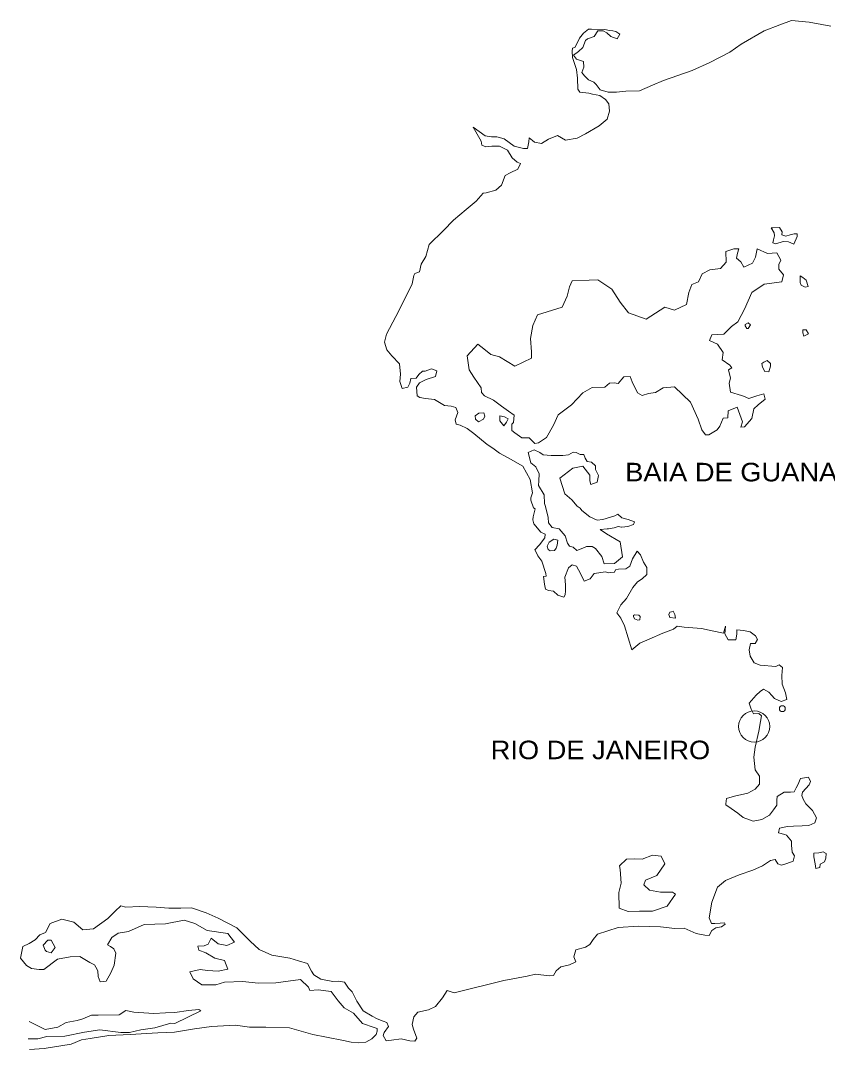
# Model space of a CAD drawing. Extents: x 47169 to 972804, y 7447977 to 9608469.
# Drawn here: x 47169 to 74653, y 7447977 to 7483012 of the extents above; entities that cross this region are included whole.
import ezdxf

# ---------------------------------------------------------------- set-up
doc = ezdxf.new("R2010")
doc.units = 0
doc.header["$LTSCALE"] = 270
doc.layers.add('1', color=7, linetype='Continuous', lineweight=13)
doc.layers.add('4', color=7, linetype='Continuous', lineweight=13)
doc.layers.add('3', color=7, linetype='Continuous')

msp = doc.modelspace()

# ---------------------------------------------------------------- linework, layer by layer
at = {"layer": '1'}
for points in [[(66771.4, 7480837.5), (66910.5, 7480652.7), (67180.5, 7480571.6), (67468.6, 7480579.8), (67786.9, 7480611), (68249.9, 7480624.2), (68697.6, 7480814.5), (69074.2, 7480969.5), (70042.9, 7481307.6), (70642.7, 7481579.9), (71333, 7481932.3), (71716.5, 7482209.5), (72496.6, 7482664.3), (73026.4, 7482867.8), (73434.2, 7483012.5), (74032.9, 7482962.6), (74467.9, 7482874.9), (74768.1, 7482816.7)], [(66647.1, 7480500.9), (66522.4, 7480541.8), (66222.7, 7480577.6), (66147.9, 7480675.4), (66137.1, 7481052.5), (66108, 7481351.4), (65972.8, 7481758.2), (65956.5, 7481968.6), (65964, 7482068.8), (66055.6, 7482104.7), (66211.7, 7482408.8), (66340.8, 7482579), (66511.9, 7482717.1), (66614.8, 7482720), (67068.2, 7482710.7), (67234.1, 7482671), (67347.6, 7482663.1), (67451.1, 7482643.9), (67577.5, 7482547.6), (67489.3, 7482389.7), (67280.9, 7482472.5), (67133.4, 7482590.4), (67018, 7482664.9), (66832.8, 7482659.6), (66704.4, 7482467.2), (66479.9, 7482394.2), (66409.4, 7482336.7), (66323.5, 7482101.2), (66172.9, 7481963.7), (66001.5, 7481836.7), (66108.5, 7481695.5), (66347.3, 7481624.6), (66353, 7481424.9), (66286.1, 7481245.4), (66382.1, 7481126.1), (66509.4, 7480996.5), (66697.1, 7480913), (66771.4, 7480837.5)], [(64675.6, 7478868.4), (64913.5, 7478830.8), (65156.6, 7478971), (65461.7, 7479101.8), (65733.9, 7478943), (66123.3, 7479009.7), (66417.9, 7479151.3), (66883.5, 7479430.9), (67144.7, 7479660.4), (67229.7, 7479929.2), (67202.2, 7480172.6), (67094.9, 7480325), (66905.6, 7480463.9), (66647.1, 7480500.9)], [(65015.3, 7463814.9), (64976.8, 7464080.2), (65069, 7464094), (65066.5, 7464182.7), (64920.7, 7464600.3), (64791.9, 7464785.3), (64726.8, 7464905.5), (64683.1, 7464993.1), (64842.7, 7465164.2), (65031.3, 7465402.7), (65038.1, 7465525), (64892.3, 7465587.4), (64657.8, 7465869.3), (64612.6, 7466012.3), (64630.3, 7466112.7), (64694.5, 7466381), (64641.9, 7466423.9), (64552.3, 7466676.6), (64549.7, 7466765.3), (64606.6, 7466933.5), (64531.8, 7467386.4), (64272, 7467834.1), (63780.2, 7468119.6), (63477.3, 7468277.4), (63256.2, 7468448.6), (63067.3, 7468576.4), (62614, 7468951.8), (62382.7, 7469122.7), (62142.7, 7469237.9), (62008.1, 7469267.3), (61972.8, 7469421.7), (62058.2, 7469668.4), (61991.7, 7469833), (61835.9, 7469884), (61609, 7469899.6), (61273.6, 7470111.9), (60963.8, 7470147.3), (60767.5, 7470174.9), (60673, 7470238.8), (60654.4, 7470526.9), (60753, 7470674.1), (60986.3, 7470791.8), (61302.5, 7470889.8), (61348.5, 7471079.9), (61161.1, 7471152.1), (60947.1, 7471079.3), (60864.8, 7471076.9), (60734.4, 7470962.1), (60645.4, 7470837.5), (60460.6, 7470821), (60424, 7470664.5), (60355.8, 7470529.3), (60172.1, 7470479.6), (60093, 7470721.5), (60106.1, 7470977.2), (60075.6, 7471320.5), (59820.7, 7471590.6), (59639.8, 7471796.2), (59570.4, 7472060.7), (59634.6, 7472329), (59946.3, 7472937.5), (60258.4, 7473534.9), (60511, 7474052.8), (60564.7, 7474331.9), (60593.6, 7474399.4), (60756.6, 7474459.6), (60810.9, 7474716.5), (60968.1, 7474976.4), (61089.9, 7475390.6), (61580.8, 7475859.9), (61920.6, 7476213.9), (62352.7, 7476581.5), (62684.5, 7476857.5), (62923.7, 7477130.8), (63026.2, 7477144.9), (63363.5, 7477232.3), (63554.1, 7477404.3), (63678.3, 7477740.8), (63840.7, 7477823.2), (64104.6, 7477952.9), (64202.1, 7478144.4), (64087.7, 7478185.5), (63918.6, 7478336.1), (63756.7, 7478597.8), (63485, 7478734.3), (63217.2, 7478737.7), (63012.1, 7478709.6), (62876.5, 7478772.3), (62862.3, 7478905.1), (62580.8, 7479385.5), (62991, 7479086.5), (63208.3, 7479048.3), (63393.5, 7479053.6), (63642.6, 7478983.1), (63979.2, 7478737.4), (64300.6, 7478657.8), (64434.4, 7478661.7), (64479.5, 7478885), (64496.2, 7479018.6), (64611.9, 7478933.2), (64675.6, 7478868.4)], [(63901.5, 7469266.5), (63961.6, 7469323.7), (63985.1, 7469579.7), (63785.9, 7469707.2), (63554.6, 7469878.1), (63281.2, 7470081.1), (62967.9, 7470238.6), (62872.2, 7470346.8), (62857.4, 7470501.8), (62610, 7470872.1), (62448.4, 7471122.8), (62383.2, 7471598.2), (62742.2, 7471997.1), (62952.7, 7471836.7), (63184.7, 7471643.5), (63485.4, 7471563.4), (64009.2, 7471245.5), (64577.7, 7471517.1), (64571.6, 7471727.9), (64538, 7472182), (64617.8, 7472628.3), (64782.4, 7472988.3), (65618.7, 7473256.5), (65783, 7473627.5), (65866.7, 7473940.7), (65963.5, 7474154.3), (66539.4, 7474170.8), (66837.7, 7474179.3), (67309.7, 7473870.9), (67590, 7473423.8), (67878.1, 7473065.7), (68481.2, 7472849.8), (69118, 7473256.4), (69440, 7473154.5), (69856.5, 7473344), (69937.5, 7473757), (70032.8, 7474026), (70256.5, 7474121.2), (70382.6, 7474391.1), (70646.6, 7474520.7), (71005.3, 7474575.2), (71205.3, 7474780.7), (71195, 7475146.7), (71459.9, 7475243), (71635, 7475236.8), (71587.7, 7475091.2), (71561.5, 7474924), (71699, 7474794.6), (71806.8, 7474620.1), (72101.6, 7474750.5), (72198.8, 7474953), (72262.7, 7475243.4), (72607.1, 7475075.5), (72925.3, 7475106.7), (73066.2, 7474855.4), (72998.2, 7474709.2), (73002.9, 7474542.8), (73162.5, 7474358.6), (73097.3, 7474112.6), (72502.4, 7474040.4), (72078.4, 7473750.9), (71826.6, 7473188.8), (71602.4, 7472749.6), (71390.5, 7472599.3), (71120.1, 7472336.4), (70894.2, 7472318.9), (70719.4, 7472314), (70632.1, 7472122.8), (70903.3, 7471997.3), (71106.8, 7471714.5), (71062.6, 7471457.9), (71325, 7471276.7), (71399.5, 7471190), (71288.3, 7471120.2), (71347.8, 7470833.3), (71311.4, 7470665.8), (71351, 7470356.1), (71724.6, 7470244.6), (71797.2, 7470224.5), (71974.5, 7470140.7), (72249.6, 7470237.2), (72484.5, 7470299.4), (72530.6, 7470123.1), (72299.5, 7469927.9), (72149, 7469790.4), (72075.9, 7469466.5), (71826.7, 7469181.9), (71703.7, 7469167.4), (71760.3, 7469346.5), (71581.4, 7469852.1), (71276.4, 7469721.3), (71262.4, 7469487.9), (71098.3, 7469472.1), (70992.7, 7469202.7), (70893.4, 7469077.8), (70610.2, 7468903.3), (70497.2, 7468900.1), (70379, 7469074.3), (70245.3, 7469436.8), (69992.1, 7470017.9), (69442.4, 7470535.1)], [(69442.4, 7470535.1), (69062.6, 7470502.1), (68799.3, 7470350.3), (68563.8, 7470310.3), (68339.2, 7470248.4), (68182.4, 7470332.7), (68007.2, 7470705.1), (67929.8, 7470891.6), (67713.9, 7470885.4), (67524.9, 7470658), (67390.6, 7470676.4), (67226.4, 7470660.6), (67065.4, 7470533.9), (66643.8, 7470521.9), (66319.9, 7470335), (65940.6, 7469924.5), (65476.9, 7469589.3), (65322.6, 7469229.6), (65087.6, 7468812.2), (64814.8, 7468637.8), (64681.8, 7468611.8), (64491, 7468806.1), (64244.2, 7468799), (64002.7, 7468969.7), (63907.6, 7469055.7), (63901.5, 7469266.5)], [(72125.4, 7455748.9), (71782.7, 7455872.3), (71603.7, 7456022.6), (71373, 7456182.5), (71194.6, 7456310.6), (71193.6, 7456343.9), (71219.4, 7456522.2), (71484.5, 7456596.4), (71944.2, 7456698.3), (72187, 7456838.4), (72336.4, 7457009.1), (72338.7, 7457286.7), (72188.9, 7457493.3), (72145.8, 7457925), (72187.4, 7458270.2), (72315.8, 7458817.8), (72378.6, 7459141.4), (72403.8, 7459341.9), (72319.4, 7459417.2), (72134.8, 7459400.9), (72058.1, 7459565.2), (71990.8, 7459763.1), (72229.8, 7460036.3), (72359.9, 7460162), (72470.8, 7460242.9), (72658.9, 7460137.2), (72764.7, 7460029.2), (72849.8, 7459931.8), (73078.9, 7459827.2), (73272.6, 7459888.2), (73224.9, 7460120), (73113.7, 7460416.5), (73105.5, 7460704.9), (73128.4, 7460983), (73012.9, 7461068.5), (72901.2, 7461021), (72365.3, 7461061.3), (72157.3, 7461144.2), (72017.1, 7461373.3), (71990.6, 7461583.4), (72035.9, 7461795.6), (72190.1, 7461800), (72268.5, 7461935.4), (72203.4, 7462055.6), (72024.6, 7462194.9), (71797, 7462243.9), (71570.3, 7462259.7), (71564.1, 7462115.2), (71538.6, 7461925.8), (71271.2, 7461929.3), (71162.7, 7462126), (71186, 7462393), (71110.7, 7462146.7), (70727.7, 7462235.7), (70365.5, 7462314.2), (69767.9, 7462352.7), (69530.3, 7462390.3), (69409.8, 7462287), (69043.4, 7462154.4), (68576.1, 7461952.3), (68261.3, 7461810.1), (67990.2, 7461580.4), (67740.3, 7462405.7), (67620, 7462657.6), (67481, 7462842.3), (67617.2, 7463112.6), (67806.4, 7463328.9), (68021.8, 7463712.5), (68181.1, 7463894.7), (68342.7, 7463999.2), (68503, 7464148.1), (68506.3, 7464392.4), (68388.2, 7464566.6), (68288.4, 7464819), (68171.5, 7464948.9), (68014.7, 7464678), (67918.9, 7464431.1), (67787.8, 7464338.5), (67541.2, 7464331.4), (67428.8, 7464306), (67400.1, 7464227.5), (67266.9, 7464212.6), (67194.9, 7464210.5), (67091.2, 7464240.9), (66701.9, 7464185.3), (66573.4, 7464004), (66370.1, 7463920.5), (66239.1, 7464183.1), (66108.4, 7464434.7), (65953, 7464474.6), (65832.5, 7464371.2), (65707.8, 7464056.8), (65725.4, 7463802), (65731.5, 7463591.3), (65725.1, 7463457.9), (65675.9, 7463378.8), (65468.1, 7463450.5), (65320.4, 7463579.5), (65155, 7463608), (65051, 7463649.4), (65015.3, 7463814.9)], [(59515.7, 7448935), (59640.2, 7448894.2), (59705.7, 7448763), (59557.9, 7448547.7), (59519.7, 7448446.7), (59627.6, 7448272.2), (59801.8, 7448288.4), (60129.1, 7448342.4), (60429.1, 7448273.5), (60604.3, 7448256.4), (60663, 7448358.1), (60551.2, 7448665.6), (60505.3, 7448830.8), (60559.4, 7449087.7), (60698.6, 7449247.2), (61066.3, 7449324.6), (61299.3, 7449442.4), (61537.3, 7449738), (61704.7, 7449987.1), (61943.5, 7449905.3), (63627.1, 7450320.7), (64424.2, 7450477), (64710.1, 7450540.8), (65174.1, 7450487.7), (65317.9, 7450491.8), (65416.1, 7450650.1), (65576.5, 7450787.9), (65862.1, 7450862.8), (66085.4, 7450958), (66018.7, 7451133.7), (66083.9, 7451368.7), (66410.2, 7451455.9), (66561.7, 7451549), (66669.9, 7451718.7), (66818.8, 7451900.6), (67521.3, 7452131.7), (68219, 7452174), (68969.9, 7452151.1), (69454.4, 7452098.4), (69772.8, 7452107.6), (70179, 7451919.4), (70478.4, 7451872.5), (70622.8, 7451854.4), (70720.7, 7452023.7), (70851.7, 7452116.2), (71045.8, 7452155.1), (71166.5, 7452247.3), (71144.7, 7452291.1), (71001.3, 7452275.9), (70816.4, 7452270.6), (70703.5, 7452267.4), (70626.2, 7452453.9), (70713.7, 7452989.2), (70904.5, 7453505.2), (71186.1, 7453724.2), (71642.8, 7453925.9), (72111.2, 7454083.5), (72446.3, 7454226.2), (72718.5, 7454411.6), (72871.7, 7454449.2), (72958.2, 7454296.3), (73093, 7454255.7), (73266.3, 7454305), (73490.1, 7454389.1), (73526.1, 7454567.7), (73450.4, 7454698.7), (73433.6, 7454931.3), (73429.8, 7455064.4), (73259.5, 7455270.5), (73197.2, 7455290.9), (72989.9, 7455351.6), (73016.3, 7455507.8), (73292.1, 7455571.1), (73497.5, 7455576.9), (73795, 7455596.5), (74021, 7455602.9), (74223.9, 7455697.4), (74280.8, 7455865.5), (74140.1, 7456116.8), (74034.2, 7456224.8), (73917.8, 7456343.6), (73831.2, 7456496.5), (73786.4, 7456628.5), (73803.8, 7456739.9), (73913.3, 7456865.1), (74033.1, 7456990.6), (74071.1, 7457102.7), (74005.4, 7457245.1), (73739.2, 7457204.3), (73642.5, 7456990.7), (73583.7, 7456889.1), (73525.8, 7456754.3), (73392.6, 7456739.4), (73176.9, 7456733.3), (72944.4, 7456593.5), (72927.6, 7456459.8), (72932.4, 7456293.5), (72813.5, 7456134.7), (72674.8, 7455953.2), (72422.1, 7455801.7), (72125.4, 7455748.9)], [(47249.5, 7451478.9), (47462.1, 7451585.2), (47663.9, 7451713.4), (47823.6, 7451873.7), (48016.4, 7451957.2), (48182, 7452262), (48578.2, 7452418.2), (48982.5, 7452308.2), (49288.4, 7452050.9), (49657.5, 7452084.2), (50140.5, 7452431.8), (50390, 7452683.5), (50579.9, 7452866.8), (50756.1, 7452816.6), (51218, 7452841.5), (51784, 7452825.1), (52217, 7452782.5), (52628.2, 7452783.6), (52987.7, 7452794.3), (53496.3, 7452631.8), (53902.8, 7452444), (54539.5, 7452118.7), (54995, 7451665.9), (55301.7, 7451375.3), (55728.7, 7451188.1), (56338.2, 7451084), (56639, 7450992.9), (56939.7, 7450901.9), (57081.1, 7450639.6), (57156.6, 7450519.7), (57397.3, 7450371.4), (57810.7, 7450294.8), (57995.6, 7450300.2), (58202.3, 7450261.9), (58341.6, 7450066.2), (58468.8, 7449936.7), (58622, 7449619.2), (58837.2, 7449292.5), (59140.5, 7449112.7), (59318, 7449018), (59515.7, 7448935)], [(59213.5, 7448726.3), (58819.1, 7448859), (58510.5, 7449216.3), (58196.9, 7449395.8), (57984.4, 7449633.8), (57749, 7449948.8), (57305.5, 7450002.3), (57018.2, 7449982.8), (56973.9, 7450092.5), (56709, 7450362.2), (55869.5, 7450248.6), (55263.6, 7450230.6), (54737.6, 7450292.8), (54111.5, 7450263.1), (53816, 7450176.6), (53343.2, 7450173.6), (53049.4, 7450375.8), (52939.4, 7450616.8), (53286.6, 7450693.7), (53534.1, 7450667.8), (53904.8, 7450645.5), (54231.8, 7450710.7), (54109.9, 7451006.9), (53788.9, 7451086.2), (53475.2, 7451265.6), (53246.3, 7451358.7), (53201.3, 7451490.6), (53426.9, 7451508.4), (53559.1, 7451556.7), (53665.8, 7451770.8), (53897.7, 7451577.9), (54197.5, 7451520.2), (54461.6, 7451627.9), (54226.7, 7451920.7), (53524.7, 7452022), (53106.3, 7452264.9), (52743.1, 7452376.2), (52109.3, 7452257.4), (51380.1, 7452235.7), (50842.3, 7451997.5), (50494.8, 7451931.6), (50283, 7451792.1), (50126, 7451543.1), (50230.7, 7451479.6), (50346, 7451405.4), (50412.3, 7451251.9), (50362.6, 7450850.7), (50247.3, 7450580.8), (50081.1, 7450298.2), (49876, 7450281), (49809.1, 7450456.6), (49803.1, 7450656.3), (49727.5, 7450776.2), (49684.1, 7450852.6), (49527.4, 7450936.7), (49182.1, 7451137.3), (48863.7, 7451127.8), (48424.1, 7451047.9), (47961.7, 7450700.9), (47797.3, 7450696), (47539.2, 7450732.6), (47371.6, 7450838.6), (47168.7, 7451087.8), (47249.5, 7451478.9)], [(47459.9, 7448931.5), (48002.6, 7448659.2), (48442.2, 7448739), (48725.4, 7448891.9), (49093.4, 7448958.5), (49286.8, 7449019.8), (49581.3, 7449139.7), (49817.5, 7449146.8), (50526.4, 7449156.9), (50758.6, 7449297.1), (51027.3, 7449249.6), (51707, 7449203.3), (52107.2, 7449226.4), (52425.5, 7449235.9), (52886, 7449305.1), (53244.8, 7449338), (53307.7, 7449295.5), (52426.5, 7448858.4), (52292.7, 7448865.5), (51742.2, 7448715.8), (51261.2, 7448646), (50883.6, 7448556.9), (50585.8, 7448548), (49863.3, 7448648.5), (49341.6, 7448566.2), (48677.8, 7448424.1), (48061.3, 7448416.7), (47755.2, 7448340.8), (47426.3, 7448342)], [(47468.2, 7447976.9), (47971, 7448003.1), (48891.5, 7448153), (49246.6, 7448308), (49543.3, 7448350.2), (50177.7, 7448447), (50906.4, 7448479.9), (51839.9, 7448541.1), (52414.6, 7448569.4), (53089.7, 7448678.3), (53673, 7448762.3), (54494.2, 7448797.8), (54968.8, 7448734.2), (55523.6, 7448739.5), (56326.2, 7448707.8), (57124.1, 7448487.1), (57589.4, 7448389.9), (58168, 7448284.8), (58426.6, 7448225.8), (58663.8, 7448199.5), (58930.1, 7448229.5), (59132.5, 7448335.4), (59282.3, 7448484.1), (59320.1, 7448596.2), (59317.5, 7448685), (59213.5, 7448726.3)]]:
    msp.add_lwpolyline(points, dxfattribs=at)
for points in [[(73111, 7475822.3), (73103.8, 7475711.1), (73238.8, 7475670.5), (73381.5, 7475718.9), (73514.6, 7475744.8), (73617.4, 7475747.7), (73619.9, 7475659), (73514, 7475400.7), (73326.7, 7475473.2), (73151.2, 7475490.4), (72896.3, 7475405.5), (72792.2, 7475447), (72820.2, 7475547.7), (72847.3, 7475681.7), (72834.2, 7475781.2), (72736.7, 7475956), (72798.4, 7475957.8), (73024.7, 7475964.1)], [(73997, 7473960.3), (73894.8, 7473935.2), (73759.2, 7473998), (73725.6, 7474097), (73729.6, 7474319.1), (73813.5, 7474265.9), (73929.4, 7474169.3)], [(72037.4, 7472650.9), (71958.5, 7472526.6), (71907.1, 7472525.2), (71853.2, 7472612.4), (71851.6, 7472667.9), (71953.2, 7472715.1)], [(73925.3, 7472482.1), (74011.7, 7472340.3), (73849, 7472269.1), (73815, 7472379.1), (73812.2, 7472478.9), (73915.1, 7472481.8)], [(72658.9, 7471047.9), (72524.6, 7471066.4), (72438.2, 7471208.2), (72424.5, 7471329.9), (72485, 7471376), (72596.5, 7471434.7), (72712.4, 7471338), (72714.9, 7471249.3)], [(62977.8, 7469539.5), (62939.6, 7469438.5), (62767.3, 7469344.8), (62661.6, 7469441.6), (62658.4, 7469552.5), (62779.2, 7469644.8), (62943.7, 7469649.6)], [(63497, 7469376.9), (63494.1, 7469476.7), (63491.9, 7469554.4), (63657.7, 7469514.8), (63783, 7469451.8), (63724.5, 7469339.1), (63635.5, 7469214.4)], [(66226.8, 7466402.8), (66290.7, 7466327), (66564.3, 7466112.8), (66804.2, 7465997.6), (66998.9, 7466025.3), (67406.9, 7466148), (67508.1, 7466206.4), (67645.5, 7466077.2), (67862.9, 7466027.9), (68081.3, 7465945.3), (68053, 7465855.7), (67849.4, 7465783.3), (67654.4, 7465766.6), (67644.1, 7465766.3), (67520.1, 7465785), (67387.8, 7465736.8), (67193.1, 7465709), (67152, 7465707.8), (66916.2, 7465678.9), (67126.3, 7465529.5), (67596.7, 7465265.5), (67673.3, 7464745.9), (67401.8, 7464527.3), (67052.4, 7464517.2), (66973.5, 7464759.2), (66749.7, 7465030.3), (66634.4, 7465104.7), (66449.4, 7465099.4), (66317, 7465051.2), (66113.7, 7464967.6), (65997.4, 7465075.3), (65872.8, 7465116.1), (65798, 7465213.9), (65718.7, 7465466.9), (65516.4, 7465705.3), (65278.4, 7465753.9), (65150.6, 7465905.7), (65145.2, 7466094.2), (65052.1, 7466469), (65018.4, 7466567.9), (65009.8, 7466867.4), (64815.5, 7467183.7), (64821.3, 7467339.3), (64835.1, 7467572.8), (64715, 7467813.5), (64546.4, 7467953), (64464.2, 7468305.8), (64667.3, 7468400.5), (64855.2, 7468306), (64970.8, 7468220.5), (65238.8, 7468206), (65640, 7468206.4), (65835, 7468223.1), (65997, 7468316.6), (66089.8, 7468308.1), (66236, 7468234.6), (66359.4, 7468238.2), (66404.3, 7468106.2), (66469.1, 7467997.1), (66613.7, 7467979), (66751.2, 7467849.8), (66754.7, 7467727.8), (66853.2, 7467519.7), (66808.2, 7467296.4), (66594.5, 7467212.6), (66559.9, 7467344.8), (66554.5, 7467533.3), (66319.4, 7467837.4), (65981.7, 7467772.2), (65539, 7467426.5), (65708.4, 7466898.5), (65950.9, 7466694.6), (66132.1, 7466477.8)], [(65409, 7465049.5), (65352.5, 7464968), (65208.9, 7464952.7), (65145.9, 7464995.3), (65111.6, 7465116.4), (65179.7, 7465251.6), (65331, 7465355.8), (65465.9, 7465315.3), (65450.1, 7465148.4)], [(68223.7, 7462763.7), (68276.4, 7462720.8), (68259, 7462609.3), (68197.7, 7462596.4), (68083.4, 7462637.5), (68050.3, 7462714.3), (68049, 7462758.7), (68079.2, 7462781.7)], [(69251.4, 7462793), (69280, 7462871.5), (69341.7, 7462873.3), (69402.7, 7462897.2), (69457.2, 7462787.8), (69481.3, 7462666.4), (69285.4, 7462683)], [(67548.8, 7453320.2), (67632.3, 7453633.4), (67588, 7454098.4), (67573.9, 7454231.2), (67803.8, 7454459.8), (68070.8, 7454467.5), (68338.5, 7454453), (68694.2, 7454596.4), (68993.3, 7454560.5), (69113.9, 7454297.6), (68847.7, 7453901.5), (68451.3, 7453745.8), (68394.5, 7453577.7), (68595, 7453394.7), (68967, 7453327.7), (69378.1, 7453328.4), (69472.4, 7453264.5), (69196.3, 7452856.9), (68697.6, 7452687.2), (68255.6, 7452685.7), (67865.4, 7452674.4), (67564.1, 7452787.9)], [(74549.5, 7454363.6), (74407.9, 7454281.9), (74390.5, 7454170.4), (74257.9, 7454133.3), (74232.7, 7454299.1), (74195.3, 7454531.1), (74191.5, 7454664.2), (74355.8, 7454668.9), (74508.9, 7454706.5), (74613.2, 7454654), (74597.4, 7454487)], [(48003.6, 7451357.3), (47937, 7451521.8), (48096.3, 7451693.1), (48209.3, 7451696.5), (48350.5, 7451445.4), (48212, 7451263.6), (48056.3, 7451314.4)]]:
    msp.add_lwpolyline(points, close=True, dxfattribs=at)
at = {"layer": '4'}
for centre, radius in [((72159, 7458974.8), 531.6), ((73116.7, 7459580.4), 100.9)]:
    msp.add_circle(centre, radius, dxfattribs=at)

# ---------------------------------------------------------------- texts
at = {"layer": '3', "width": 1.1}
for s, height, p in [('BAIA DE GUANABARA', 631.2, (67764.2, 7467321.3)), ('RIO DE JANEIRO', 630.9, (63182.1, 7457860.6))]:
    msp.add_text(s, height=height, dxfattribs=at).set_placement(p)

doc.saveas('drawing.dxf')
